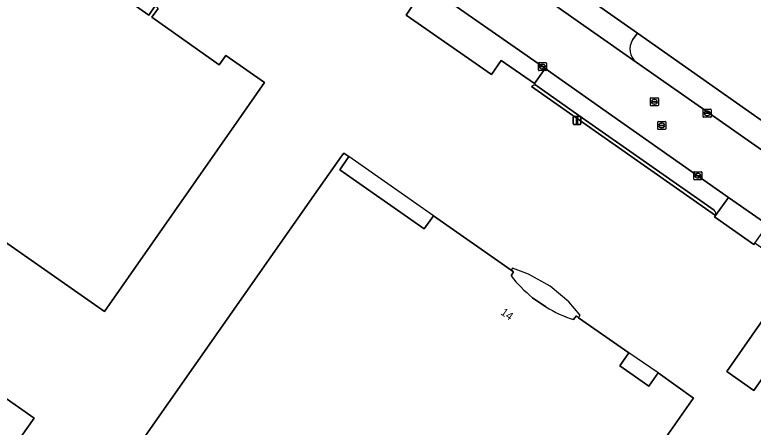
# Model space of a CAD drawing. Extents: x 155018 to 156648, y 383979 to 385733.
# Drawn here: x 155390.3 to 155482.6, y 384711 to 384762.6 of the extents above; entities that cross this region are included whole.
import ezdxf

# ---------------------------------------------------------------- set-up
doc = ezdxf.new("R2010")
doc.units = 0
for name, color, linetype in [('IMGEO_Erf', 7, 'Continuous'), ('IMGEO_Kolk', 7, 'Continuous'), ('IMGEO_Lichtmast', 7, 'Continuous'), ('IMGEO_Pand', 7, 'Continuous'), ('IMGEO_Pand_nummerreeks', 7, 'Continuous'), ('IMGEO_Pand_overbouw', 7, 'Continuous'), ('IMGEO_Parkeervlak_open', 7, 'Continuous'), ('IMGEO_Rijbaan_lokaal_gesloten', 7, 'Continuous'), ('IMGEO_Rioolput', 7, 'Continuous'), ('IMGEO_Voetpad_open', 7, 'Continuous')]:
    doc.layers.add(name, color=color, linetype=linetype)

msp = doc.modelspace()

# ---------------------------------------------------------------- linework, layer by layer
at = {"layer": 'IMGEO_Erf'}
for points in [[(155341.136, 384849.344), (155357.104, 384838.097), (155388.182, 384816.31), (155437.864, 384781.52), (155468.111, 384760.264), (155482.743, 384750), (155497.007, 384739.994), (155500, 384737.848), (155500.185, 384737.718), (155505.292, 384734.131), (155525.191, 384720.19), (155529.43, 384717.209), (155537.244, 384711.718), (155537.392, 384711.902)], [(155455.525, 384753.704), (155455.245, 384753.973), (155451.096, 384756.854), (155449.87, 384755.133), (155439.233, 384762.528), (155440.155, 384763.897), (155361.769, 384818.945), (155361.486, 384818.938), (155361.268, 384818.932), (155354.808, 384823.467)], [(155380.295, 384795.715), (155400.987, 384781.219), (155394.985, 384772.673), (155399.401, 384769.578), (155398.613, 384768.476), (155407.047, 384762.521), (155407.847, 384763.684), (155408.247, 384763.388), (155407.436, 384762.27), (155415.863, 384756.329), (155416.674, 384757.499), (155421.517, 384754.124), (155418.633, 384750), (155401.505, 384725.502), (155370.384, 384747.304)], [(155494.391, 384725.808), (155491.992, 384727.456), (155491.434, 384727.977), (155488.002, 384730.369), (155482.78, 384734.037), (155482.651, 384733.867), (155477.731, 384737.307), (155477.853, 384737.491), (155460.043, 384750), (155454.881, 384753.626)], [(155460.147, 384724.48), (155460.497, 384724.953), (155460.765, 384724.715), (155467.041, 384720.332), (155465.901, 384718.699), (155469.543, 384716.164), (155470.699, 384717.809), (155475.122, 384714.676), (155474.887, 384714.341), (155472.254, 384710.581), (155437.627, 384661.151), (155393.906, 384691.785), (155428.283, 384740.809), (155431.153, 384744.902), (155431.435, 384745.293), (155432.05, 384744.855), (155430.91, 384743.203), (155441.482, 384735.835), (155442.622, 384737.466), (155452.328, 384730.665), (155452.641, 384730.445)], [(155361.229, 384734.221), (155392.717, 384712.158), (155390.399, 384708.873)], [(155452.641, 384730.445), (155452.326, 384729.961)], [(155455.012, 384727.216), (155456.658, 384726.075)]]:
    msp.add_lwpolyline(points, dxfattribs=at)
msp.add_lwpolyline([(155487.753, 384722.907), (155482.657, 384715.617), (155479.302, 384717.992), (155484.368, 384725.279)], close=True, dxfattribs=at)
for centre, radius, start, end in [((155455.26, 384753.197), 0.573, 62.40494, 131.40689), ((155465.692, 384740.353), 16.93, 217.86494, 230.89024), ((155465.042, 384739.801), 16.084, 238.58305, 252.28184)]:
    msp.add_arc(centre, radius, start, end, dxfattribs=at)
at = {"layer": 'IMGEO_Kolk'}
for p, q in [((155455.742, 384755.682), (155455.742, 384756.534)), ((155455.817, 384756.608), (155456.669, 384756.608)), ((155456.001, 384756.102), (155456.001, 384756.114)), ((155456.439, 384756.065), (155456.041, 384756.065)), ((155456.044, 384756.151), (155456.442, 384756.151)), ((155456.253, 384755.828), (155456.228, 384755.828)), ((155456.23, 384756.388), (155456.255, 384756.388)), ((155456.485, 384756.114), (155456.485, 384756.102)), ((155456.743, 384756.534), (155456.743, 384755.682)), ((155456.669, 384755.608), (155455.817, 384755.608)), ((155476.33, 384749.839), (155476.33, 384750.691)), ((155476.405, 384750.765), (155477.257, 384750.765)), ((155476.589, 384750.259), (155476.589, 384750.271)), ((155476.632, 384750.308), (155477.03, 384750.308)), ((155476.818, 384750.545), (155476.843, 384750.545)), ((155477.073, 384750.271), (155477.073, 384750.259)), ((155477.331, 384750.691), (155477.331, 384749.839)), ((155477.257, 384749.765), (155476.405, 384749.765)), ((155477.027, 384750.222), (155476.629, 384750.222)), ((155476.841, 384749.985), (155476.816, 384749.985)), ((155475.159, 384742.038), (155475.159, 384742.89)), ((155475.234, 384742.964), (155476.086, 384742.964)), ((155476.16, 384742.89), (155476.16, 384742.038)), ((155476.086, 384741.964), (155475.234, 384741.964)), ((155475.418, 384742.458), (155475.418, 384742.47)), ((155475.856, 384742.421), (155475.458, 384742.421)), ((155475.461, 384742.507), (155475.859, 384742.507)), ((155475.67, 384742.184), (155475.645, 384742.184)), ((155475.647, 384742.744), (155475.672, 384742.744)), ((155475.902, 384742.47), (155475.902, 384742.458))]:
    msp.add_line(p, q, dxfattribs=at)
for points in [[(155455.742, 384755.682), (155455.742, 384756.534)], [(155455.817, 384756.608), (155456.669, 384756.608)], [(155456.743, 384756.534), (155456.743, 384755.682)], [(155456.669, 384755.608), (155455.817, 384755.608)], [(155476.33, 384749.839), (155476.33, 384750.691)], [(155476.405, 384750.765), (155477.257, 384750.765)], [(155477.331, 384750.691), (155477.331, 384749.839)], [(155477.257, 384749.765), (155476.405, 384749.765)], [(155475.159, 384742.038), (155475.159, 384742.89)], [(155475.234, 384742.964), (155476.086, 384742.964)], [(155476.16, 384742.89), (155476.16, 384742.038)], [(155476.086, 384741.964), (155475.234, 384741.964)]]:
    msp.add_lwpolyline(points, dxfattribs=at)
for centre, radius, start, end in [((155455.819, 384756.532), 0.0765, 91.55205, 178.44795), ((155455.819, 384756.532), 0.0765, 91.55205, 178.44795), ((155456.041, 384756.111), 0.0403, 85.87752, 175.75265), ((155456.038, 384756.101), 0.0366, 178.93798, 274.71019), ((155456.442, 384756.108), 0.043, 264.86636, 352.45326), ((155456.446, 384756.113), 0.0386, 1.73085, 96.63898), ((155456.667, 384756.532), 0.0765, 1.55205, 88.44795), ((155456.667, 384756.532), 0.0765, 1.55205, 88.44795), ((155455.819, 384755.684), 0.0765, 181.55205, 268.44795), ((155455.819, 384755.684), 0.0765, 181.55205, 268.44795), ((155456.667, 384755.684), 0.0765, 271.55205, 358.44795), ((155456.667, 384755.684), 0.0765, 271.55205, 358.44795), ((155476.407, 384750.689), 0.0765, 91.55205, 178.44795), ((155476.407, 384750.689), 0.0765, 91.55205, 178.44795), ((155476.629, 384750.268), 0.0403, 85.87752, 175.75265), ((155476.626, 384750.258), 0.0366, 178.93798, 274.71019), ((155477.03, 384750.265), 0.043, 264.86636, 352.45326), ((155477.034, 384750.27), 0.0386, 1.73085, 96.63898), ((155477.255, 384750.689), 0.0765, 1.55205, 88.44795), ((155477.255, 384750.689), 0.0765, 1.55205, 88.44795), ((155476.407, 384749.841), 0.0765, 181.55205, 268.44795), ((155476.407, 384749.841), 0.0765, 181.55205, 268.44795), ((155477.255, 384749.841), 0.0765, 271.55205, 358.44795), ((155477.255, 384749.841), 0.0765, 271.55205, 358.44795), ((155475.236, 384742.888), 0.0765, 91.55205, 178.44795), ((155475.236, 384742.888), 0.0765, 91.55205, 178.44795), ((155476.084, 384742.888), 0.0765, 1.55205, 88.44795), ((155476.084, 384742.888), 0.0765, 1.55205, 88.44795), ((155475.236, 384742.04), 0.0765, 181.55205, 268.44795), ((155475.236, 384742.04), 0.0765, 181.55205, 268.44795), ((155475.458, 384742.467), 0.0403, 85.87752, 175.75265), ((155475.455, 384742.457), 0.0366, 178.93798, 274.71019), ((155475.859, 384742.464), 0.043, 264.86636, 352.45326), ((155475.863, 384742.469), 0.0386, 1.73085, 96.63898), ((155476.084, 384742.04), 0.0765, 271.55205, 358.44795), ((155476.084, 384742.04), 0.0765, 271.55205, 358.44795)]:
    msp.add_arc(centre, radius, start, end, dxfattribs=at)
for centre, major_axis, ratio, start_param, end_param in [((155456.229, 384756.108), (-0.387, 0.002), 0.722429, 4.712389, 7.853982), ((155456.254, 384756.108), (-0.39, 0.002), 0.717154, 1.570796, 4.712389), ((155476.817, 384750.265), (-0.387, 0.002), 0.722429, 4.712389, 7.853982), ((155476.842, 384750.265), (-0.39, 0.002), 0.717154, 1.570796, 4.712389), ((155475.646, 384742.464), (-0.387, 0.002), 0.722429, 4.712389, 7.853982), ((155475.671, 384742.464), (-0.39, 0.002), 0.717154, 1.570796, 4.712389)]:
    msp.add_ellipse(centre, major_axis=major_axis, ratio=ratio, start_param=start_param, end_param=end_param, dxfattribs=at)
at = {"layer": 'IMGEO_Lichtmast'}
for p, q in [((155460.066, 384748.977), (155460.066, 384749.777)), ((155460.066, 384749.777), (155460.066, 384748.977)), ((155460.166, 384749.877), (155460.956, 384749.877)), ((155460.956, 384749.877), (155460.166, 384749.877)), ((155461.056, 384749.777), (155461.056, 384748.977)), ((155461.056, 384748.977), (155461.056, 384749.777)), ((155460.956, 384748.877), (155460.166, 384748.877)), ((155460.166, 384748.877), (155460.956, 384748.877))]:
    msp.add_line(p, q, dxfattribs=at)
msp.add_lwpolyline([(155460.486, 384749.752), (155460.636, 384749.752), (155460.636, 384749.002), (155460.486, 384749.002), (155460.486, 384749.752)], dxfattribs=at)
for centre, start, end in [((155460.166, 384749.777), 90, 180), ((155460.166, 384749.777), 90, 180), ((155460.956, 384749.777), 0, 90), ((155460.956, 384749.777), 360, 90), ((155460.166, 384748.977), 180, 270), ((155460.166, 384748.977), 180, 270), ((155460.956, 384748.977), 270, 0), ((155460.956, 384748.977), 270, 0)]:
    msp.add_arc(centre, 0.1, start, end, dxfattribs=at)
at = {"layer": 'IMGEO_Pand'}
for points in [[(155370.384, 384747.304), (155401.505, 384725.502), (155418.633, 384750), (155421.517, 384754.124), (155416.674, 384757.499), (155415.863, 384756.329), (155407.436, 384762.27), (155408.247, 384763.388), (155407.847, 384763.684), (155407.047, 384762.521), (155398.613, 384768.476), (155399.401, 384769.578), (155394.985, 384772.673), (155400.987, 384781.219), (155380.295, 384795.715)], [(155452.326, 384729.961), (155452.641, 384730.445), (155452.328, 384730.665), (155442.622, 384737.466), (155441.482, 384735.835), (155430.91, 384743.203), (155432.05, 384744.855), (155431.435, 384745.293), (155431.153, 384744.902), (155428.283, 384740.809), (155393.906, 384691.785), (155437.627, 384661.151), (155472.254, 384710.581), (155474.887, 384714.341), (155475.122, 384714.676), (155470.699, 384717.809), (155469.543, 384716.164), (155465.901, 384718.699), (155467.041, 384720.332), (155460.765, 384724.715), (155460.497, 384724.953), (155460.147, 384724.48)], [(155390.399, 384708.873), (155392.717, 384712.158), (155361.229, 384734.221)], [(155456.658, 384726.075), (155455.012, 384727.216)]]:
    msp.add_lwpolyline(points, dxfattribs=at)
msp.add_lwpolyline([(155479.302, 384717.992), (155482.657, 384715.617), (155487.753, 384722.907), (155484.368, 384725.279)], close=True, dxfattribs=at)
for centre, radius, start, end in [((155465.692, 384740.353), 16.93, 217.86494, 230.89024), ((155465.042, 384739.801), 16.084, 238.58305, 252.28184)]:
    msp.add_arc(centre, radius, start, end, dxfattribs=at)
at = {"layer": 'IMGEO_Pand_overbouw'}
for points in [[(155441.482, 384735.835), (155442.622, 384737.466), (155432.05, 384744.855), (155430.91, 384743.203)], [(155467.041, 384720.332), (155465.901, 384718.699), (155469.543, 384716.164), (155470.699, 384717.809)]]:
    msp.add_lwpolyline(points, close=True, dxfattribs=at)
for points in [[(155460.147, 384724.48), (155460.497, 384724.953), (155460.765, 384724.715), (155460.95, 384725.026), (155459.531, 384726.685), (155457.192, 384728.654), (155454.521, 384730.173), (155452.518, 384730.926), (155452.328, 384730.665)], [(155452.328, 384730.665), (155452.641, 384730.445), (155452.326, 384729.961)], [(155455.012, 384727.216), (155456.658, 384726.075)]]:
    msp.add_lwpolyline(points, dxfattribs=at)
for centre, radius, start, end in [((155465.692, 384740.353), 16.93, 217.86494, 230.89024), ((155465.042, 384739.801), 16.084, 238.58305, 252.28184)]:
    msp.add_arc(centre, radius, start, end, dxfattribs=at)
at = {"layer": 'IMGEO_Parkeervlak_open'}
msp.add_lwpolyline([(155477.853, 384737.491), (155479.512, 384739.757), (155464.924, 384750), (155456.592, 384755.849), (155455.245, 384753.973), (155455.525, 384753.704), (155460.804, 384750), (155477.712, 384738.137)], dxfattribs=at)
msp.add_arc((155477.41, 384737.733), 0.505, 331.41457, 53.21069, dxfattribs=at)
at = {"layer": 'IMGEO_Rijbaan_lokaal_gesloten'}
for points in [[(155494.889, 384737.794), (155477.483, 384750), (155467.973, 384756.67), (155434.551, 384780.106), (155388.019, 384812.731), (155353.81, 384836.716)], [(155356.562, 384825.996), (155363.162, 384821.376), (155382.366, 384807.915), (155389.497, 384802.9), (155391.658, 384801.391), (155397.713, 384797.165), (155436.329, 384770.061), (155438.804, 384768.318), (155441.642, 384766.318), (155456.242, 384756.107), (155456.592, 384755.849), (155464.924, 384750), (155479.512, 384739.757), (155484.418, 384736.312)]]:
    msp.add_lwpolyline(points, dxfattribs=at)
at = {"layer": 'IMGEO_Rioolput'}
for p, q in [((155469.736, 384751.276), (155469.736, 384752.128)), ((155469.811, 384752.202), (155470.663, 384752.202)), ((155470.737, 384752.128), (155470.737, 384751.276)), ((155470.663, 384751.202), (155469.811, 384751.202)), ((155469.995, 384751.696), (155469.995, 384751.708)), ((155470.433, 384751.659), (155470.035, 384751.659)), ((155470.038, 384751.745), (155470.436, 384751.745)), ((155470.247, 384751.422), (155470.222, 384751.422)), ((155470.224, 384751.982), (155470.249, 384751.982)), ((155470.479, 384751.708), (155470.479, 384751.696)), ((155470.649, 384748.318), (155470.649, 384749.17)), ((155470.724, 384749.244), (155471.576, 384749.244)), ((155470.908, 384748.738), (155470.908, 384748.75)), ((155471.346, 384748.701), (155470.948, 384748.701)), ((155470.951, 384748.787), (155471.349, 384748.787)), ((155471.16, 384748.464), (155471.135, 384748.464)), ((155471.137, 384749.024), (155471.162, 384749.024)), ((155471.392, 384748.75), (155471.392, 384748.738)), ((155471.65, 384749.17), (155471.65, 384748.318)), ((155471.576, 384748.244), (155470.724, 384748.244))]:
    msp.add_line(p, q, dxfattribs=at)
for points in [[(155469.736, 384751.276), (155469.736, 384752.128)], [(155469.811, 384752.202), (155470.663, 384752.202)], [(155470.737, 384752.128), (155470.737, 384751.276)], [(155470.663, 384751.202), (155469.811, 384751.202)], [(155470.649, 384748.318), (155470.649, 384749.17)], [(155470.724, 384749.244), (155471.576, 384749.244)], [(155471.65, 384749.17), (155471.65, 384748.318)], [(155471.576, 384748.244), (155470.724, 384748.244)]]:
    msp.add_lwpolyline(points, dxfattribs=at)
for centre, radius, start, end in [((155469.813, 384752.126), 0.0765, 91.55205, 178.44795), ((155469.813, 384752.126), 0.0765, 91.55205, 178.44795), ((155470.661, 384752.126), 0.0765, 1.55205, 88.44795), ((155470.661, 384752.126), 0.0765, 1.55205, 88.44795), ((155469.813, 384751.278), 0.0765, 181.55205, 268.44795), ((155469.813, 384751.278), 0.0765, 181.55205, 268.44795), ((155470.035, 384751.705), 0.0403, 85.87752, 175.75265), ((155470.032, 384751.695), 0.0366, 178.93798, 274.71019), ((155470.436, 384751.702), 0.043, 264.86636, 352.45326), ((155470.44, 384751.707), 0.0386, 1.73085, 96.63898), ((155470.661, 384751.278), 0.0765, 271.55205, 358.44795), ((155470.661, 384751.278), 0.0765, 271.55205, 358.44795), ((155470.726, 384749.168), 0.0765, 91.55205, 178.44795), ((155470.726, 384749.168), 0.0765, 91.55205, 178.44795), ((155470.948, 384748.747), 0.0403, 85.87752, 175.75265), ((155470.945, 384748.737), 0.0366, 178.93798, 274.71019), ((155471.349, 384748.744), 0.043, 264.86636, 352.45326), ((155471.353, 384748.749), 0.0386, 1.73085, 96.63898), ((155471.574, 384749.168), 0.0765, 1.55205, 88.44795), ((155471.574, 384749.168), 0.0765, 1.55205, 88.44795), ((155470.726, 384748.32), 0.0765, 181.55205, 268.44795), ((155470.726, 384748.32), 0.0765, 181.55205, 268.44795), ((155471.574, 384748.32), 0.0765, 271.55205, 358.44795), ((155471.574, 384748.32), 0.0765, 271.55205, 358.44795)]:
    msp.add_arc(centre, radius, start, end, dxfattribs=at)
for centre, major_axis, ratio, start_param, end_param in [((155470.223, 384751.702), (-0.387, 0.002), 0.722429, 4.712389, 7.853982), ((155470.248, 384751.702), (-0.39, 0.002), 0.717154, 1.570796, 4.712389), ((155471.136, 384748.744), (-0.387, 0.002), 0.722429, 4.712389, 7.853982), ((155471.161, 384748.744), (-0.39, 0.002), 0.717154, 1.570796, 4.712389)]:
    msp.add_ellipse(centre, major_axis=major_axis, ratio=ratio, start_param=start_param, end_param=end_param, dxfattribs=at)
at = {"layer": 'IMGEO_Voetpad_open'}
for points in [[(155467.515, 384759.441), (155468.111, 384760.264), (155437.864, 384781.52), (155437.289, 384780.642)], [(155434.551, 384780.106), (155467.973, 384756.67)], [(155440.155, 384763.897), (155439.233, 384762.528), (155449.87, 384755.133), (155451.096, 384756.854), (155455.245, 384753.973), (155456.592, 384755.849), (155456.242, 384756.107), (155441.642, 384766.318)], [(155495.604, 384737.917), (155496.696, 384739.297), (155497.007, 384739.994), (155482.743, 384750), (155468.111, 384760.264), (155467.515, 384759.441)], [(155467.973, 384756.67), (155477.483, 384750), (155494.889, 384737.794)], [(155454.881, 384753.626), (155460.043, 384750), (155477.853, 384737.491)], [(155477.712, 384738.137), (155460.804, 384750), (155455.525, 384753.704)]]:
    msp.add_lwpolyline(points, dxfattribs=at)
msp.add_lwpolyline([(155477.853, 384737.491), (155477.731, 384737.307), (155482.651, 384733.867), (155482.78, 384734.037), (155484.418, 384736.312), (155479.512, 384739.757)], close=True, dxfattribs=at)
for centre, radius, start, end in [((155469.237, 384758.302), 2.064, 146.51624, 232.25413), ((155469.237, 384758.302), 2.064, 146.51624, 232.25413), ((155455.26, 384753.197), 0.573, 62.40494, 131.40689), ((155477.41, 384737.733), 0.505, 331.41457, 53.21069)]:
    msp.add_arc(centre, radius, start, end, dxfattribs=at)

# ---------------------------------------------------------------- texts
at = {"layer": 'IMGEO_Pand_nummerreeks'}
msp.add_text('14', height=1, rotation=324.94079, dxfattribs=at).set_placement((155450.937, 384725.193))

doc.saveas('drawing.dxf')
